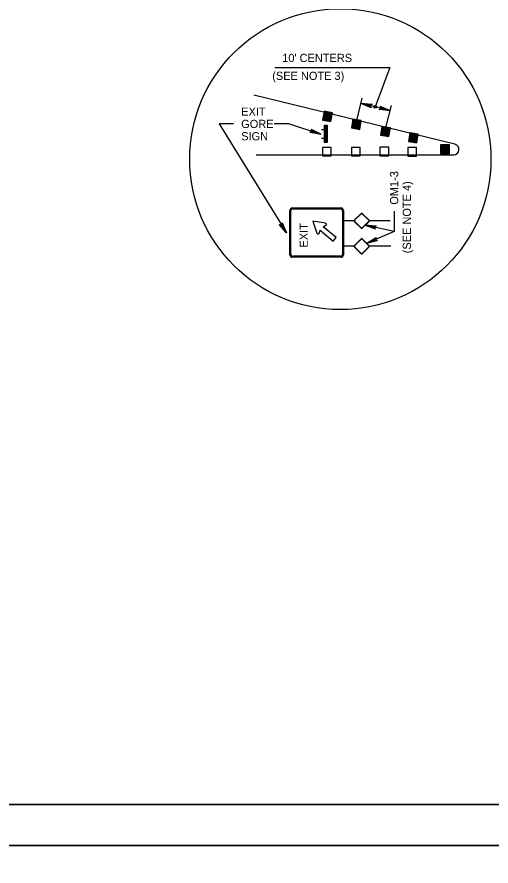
# Model space of a CAD drawing. Extents: x 640253 to 641999, y 298458 to 299646.
# Drawn here: x 641348.1 to 641521.2, y 299044.1 to 299354.5 of the extents above; entities that cross this region are included whole.
import ezdxf

# ---------------------------------------------------------------- set-up
doc = ezdxf.new("R2010")
doc.units = 0
for name, color, linetype in [('1', 7, 'Continuous'), ('2', 7, 'Continuous'), ('PLT-BNDY', 7, 'Continuous')]:
    doc.layers.add(name, color=color, linetype=linetype)

msp = doc.modelspace()

# ---------------------------------------------------------------- linework, layer by layer
at = {"layer": '1'}
for p, q in [((641448.54, 299284.66), (641466.48, 299284.66)), ((641448.77, 299284.33), (641466.25, 299284.33)), ((641447.76, 299267.56), (641447.76, 299283.76)), ((641448.05, 299267.83), (641448.05, 299283.49)), ((641466.97, 299283.49), (641466.97, 299267.83)), ((641467.26, 299283.76), (641467.26, 299267.56)), ((641471.26, 299280.16), (641473.79, 299282.69)), ((641471.39, 299280.15), (641473.81, 299282.56)), ((641474.16, 299282.56), (641476.58, 299280.15)), ((641474.18, 299282.69), (641476.71, 299280.16)), ((641460.69, 299279.14), (641456.07, 299279.87)), ((641456.07, 299279.87), (641457.61, 299275.45)), ((641459.89, 299277.79), (641460.91, 299278.41)), ((641471.18, 299279.96), (641466.97, 299279.96)), ((641473.79, 299277.24), (641471.26, 299279.77)), ((641473.81, 299277.37), (641471.39, 299279.79)), ((641476.58, 299279.79), (641474.16, 299277.37)), ((641476.71, 299279.77), (641474.18, 299277.24)), ((641484.35, 299279.96), (641476.79, 299279.96)), ((641458.38, 299275.37), (641458.79, 299276.49)), ((641458.79, 299276.49), (641463.53, 299272.55)), ((641464.62, 299273.86), (641459.89, 299277.79)), ((641463.53, 299272.55), (641464.62, 299273.86)), ((641471.26, 299270.85), (641473.79, 299273.39)), ((641471.39, 299270.84), (641473.81, 299273.26)), ((641474.16, 299273.26), (641476.58, 299270.84)), ((641474.18, 299273.39), (641476.71, 299270.85)), ((641471.18, 299270.7), (641466.97, 299270.7)), ((641473.79, 299267.93), (641471.26, 299270.47)), ((641473.81, 299268.06), (641471.39, 299270.48)), ((641476.58, 299270.48), (641474.16, 299268.06)), ((641476.71, 299270.47), (641474.18, 299267.93)), ((641484.56, 299270.7), (641476.79, 299270.7)), ((641466.48, 299266.66), (641448.54, 299266.66)), ((641466.25, 299267), (641448.77, 299267)), ((641920.31, 299066.63), (641134.31, 299066.63)), ((641134.31, 299066.63), (641720.31, 299066.63))]:
    msp.add_line(p, q, dxfattribs=at)
for centre, radius, start, end in [((641473.99, 299282.5), 0.275, 45, 135), ((641473.99, 299282.38), 0.252, 45, 135), ((641471.46, 299279.97), 0.275, 135, 225), ((641471.57, 299279.97), 0.252, 135, 225), ((641476.4, 299279.97), 0.252, 315, 45), ((641476.52, 299279.97), 0.275, 315, 45), ((641473.99, 299277.44), 0.275, 225, 315), ((641473.99, 299277.55), 0.252, 225, 315), ((641473.99, 299273.19), 0.275, 45, 135), ((641473.99, 299273.08), 0.252, 45, 135), ((641471.46, 299270.66), 0.275, 135, 225), ((641471.57, 299270.66), 0.252, 135, 225), ((641476.4, 299270.66), 0.252, 315, 45), ((641476.52, 299270.66), 0.275, 315, 45), ((641473.99, 299268.13), 0.275, 225, 315), ((641473.99, 299268.24), 0.252, 225, 315)]:
    msp.add_arc(centre, radius, start, end, dxfattribs=at)
for centre, major_axis, start_param, end_param in [((641448.54, 299283.76), (0, -0.9), 3.141593, 4.712389), ((641448.77, 299283.49), (0, -0.833), 3.141593, 4.712389), ((641466.25, 299283.49), (0, 0.833), 4.712389, 6.283185), ((641466.48, 299283.76), (0, 0.9), 4.712389, 6.283185), ((641460.66, 299278.75), (0.336, -0.279), 6.014589, 8.386103), ((641457.99, 299275.56), (-0.339, 0.282), 1.019875, 3.40872), ((641448.54, 299267.56), (0, -0.9), 4.712389, 6.283185), ((641448.77, 299267.83), (0, -0.833), 4.712389, 6.283185), ((641466.25, 299267.83), (0, 0.833), 3.141593, 4.712389), ((641466.48, 299267.56), (0, 0.9), 3.141593, 4.712389)]:
    msp.add_ellipse(centre, major_axis=major_axis, ratio=0.866667, start_param=start_param, end_param=end_param, dxfattribs=at)
at = {"layer": '2'}
for p, q in [((641508.04, 299307.94), (641434.6, 299325.94)), ((641472.23, 299316.68), (641474.19, 299324.75)), ((641484.34, 299320.29), (641473.74, 299322.88)), ((641482.83, 299314.1), (641484.79, 299322.16)), ((641421.94, 299315.4), (641446.55, 299275.57)), ((641427.15, 299315.4), (641421.94, 299315.4)), ((641460.38, 299313.23), (641459.34, 299313.23)), ((641460.71, 299308.85), (641460.71, 299314.64)), ((641461.05, 299308.77), (641461.05, 299314.73)), ((641460.38, 299310.02), (641459.34, 299310.02)), ((641435.45, 299304.08), (641507.56, 299304.08)), ((641485.84, 299283.45), (641485.84, 299276.05)), ((641485.84, 299276.05), (641475.26, 299278.32)), ((641485.84, 299276.05), (641475.82, 299271.75))]:
    msp.add_line(p, q, dxfattribs=at)
for points in [[(641442.27, 299335.98), (641484.21, 299335.98), (641478.83, 299321.62)], [(641477.3, 299321.52), (641477.23, 299321.82), (641473.74, 299322.88), (641477.3, 299321.52), (641477.45, 299321.32), (641473.74, 299322.88), (641477.32, 299322.19), (641477.51, 299322.43), (641473.74, 299322.88), (641477.75, 299322.55), (641477.51, 299322.43)], [(641480.78, 299321.65), (641480.85, 299321.35), (641484.34, 299320.29), (641480.78, 299321.65), (641480.63, 299321.86), (641484.34, 299320.29), (641480.76, 299320.98), (641480.57, 299320.75), (641484.34, 299320.29), (641480.32, 299320.62), (641480.57, 299320.75)], [(641462.72, 299316.25), (641463.28, 299319.45), (641460.21, 299319.99), (641459.65, 299316.79), (641462.72, 299316.25), (641460.25, 299319.93), (641459.71, 299316.83), (641462.69, 299316.31), (641463.23, 299319.41), (641460.31, 299319.91), (641459.78, 299316.89), (641462.64, 299316.38), (641463.16, 299319.35), (641460.37, 299319.83), (641459.86, 299316.93), (641462.6, 299316.45), (641463.1, 299319.31), (641460.41, 299319.78), (641459.92, 299316.98), (641462.57, 299316.51), (641463.03, 299319.25), (641460.45, 299319.69), (641459.98, 299317.02), (641462.53, 299316.57), (641462.97, 299319.2), (641460.5, 299319.62), (641460.06, 299317.07), (641462.48, 299316.64), (641462.91, 299319.16), (641460.55, 299319.55), (641460.12, 299317.11), (641462.42, 299316.7), (641462.83, 299319.1), (641460.61, 299319.48), (641460.2, 299317.18), (641462.39, 299316.76), (641462.75, 299319.03), (641460.65, 299319.4), (641460.27, 299317.23), (641462.35, 299316.83), (641462.69, 299318.98), (641460.68, 299319.32), (641460.34, 299317.28), (641462.33, 299316.9), (641462.62, 299318.91), (641460.73, 299319.23), (641460.43, 299317.34), (641461.32, 299317.14), (641462.28, 299316.98), (641462.55, 299318.86), (641460.8, 299319.14), (641460.53, 299317.39), (641462.23, 299317.06), (641462.48, 299318.8), (641460.85, 299319.06), (641460.62, 299317.46), (641462.18, 299317.16), (641462.4, 299318.7), (641460.94, 299318.94), (641460.73, 299317.56), (641462.09, 299317.27), (641462.3, 299318.6), (641461, 299318.8), (641460.85, 299317.67), (641462.01, 299317.4), (641462.02, 299317.41), (641462.16, 299318.5), (641461.1, 299318.67), (641460.98, 299317.76), (641461.93, 299317.54), (641462.03, 299318.39), (641461.21, 299318.54), (641461.11, 299317.86), (641461.82, 299317.7), (641461.9, 299318.28), (641461.29, 299318.36), (641461.25, 299317.98), (641461.74, 299317.87), (641461.76, 299318.15), (641461.4, 299318.22), (641461.35, 299318.1), (641461.64, 299318.04)], [(641442.03, 299315.49), (641447.23, 299315.49), (641459.05, 299311.68)], [(641473.25, 299313.37), (641473.81, 299316.57), (641470.73, 299317.11), (641470.18, 299313.91), (641473.25, 299313.37), (641470.78, 299317.05), (641470.24, 299313.96), (641473.22, 299313.44), (641473.76, 299316.53), (641470.84, 299317.04), (641470.31, 299314.01), (641473.17, 299313.51), (641473.69, 299316.47), (641470.9, 299316.95), (641470.39, 299314.05), (641473.13, 299313.57), (641473.63, 299316.43), (641470.94, 299316.9), (641470.45, 299314.1), (641473.09, 299313.64), (641473.56, 299316.37), (641470.98, 299316.82), (641470.51, 299314.15), (641473.06, 299313.69), (641473.5, 299316.33), (641471.03, 299316.74), (641470.58, 299314.19), (641473.01, 299313.76), (641473.43, 299316.28), (641471.08, 299316.68), (641470.65, 299314.24), (641472.95, 299313.82), (641473.36, 299316.22), (641471.14, 299316.61), (641470.73, 299314.3), (641472.92, 299313.88), (641473.28, 299316.15), (641471.17, 299316.52), (641470.8, 299314.35), (641472.88, 299313.95), (641473.22, 299316.1), (641471.21, 299316.45), (641470.87, 299314.4), (641472.86, 299314.03), (641473.15, 299316.03), (641471.26, 299316.36), (641470.96, 299314.47), (641471.85, 299314.27), (641472.81, 299314.1), (641473.08, 299315.98), (641471.33, 299316.26), (641471.05, 299314.51), (641472.76, 299314.18), (641473.01, 299315.92), (641471.38, 299316.18), (641471.15, 299314.59), (641472.71, 299314.28), (641472.93, 299315.83), (641471.47, 299316.06), (641471.26, 299314.68), (641472.62, 299314.4), (641472.82, 299315.72), (641471.53, 299315.93), (641471.38, 299314.79), (641472.54, 299314.53), (641472.54, 299314.53), (641472.69, 299315.62), (641471.63, 299315.8), (641471.51, 299314.88), (641472.46, 299314.66), (641472.56, 299315.51), (641471.74, 299315.66), (641471.64, 299314.98), (641472.35, 299314.82), (641472.43, 299315.4), (641471.82, 299315.48), (641471.77, 299315.1), (641472.27, 299314.99), (641472.29, 299315.28), (641471.93, 299315.34), (641471.88, 299315.23), (641472.17, 299315.16)], [(641455.6, 299313.31), (641455.65, 299313), (641459.05, 299311.68), (641455.6, 299313.31), (641455.47, 299313.52), (641459.05, 299311.68), (641455.53, 299312.64), (641455.32, 299312.42), (641459.05, 299311.68), (641455.07, 299312.31), (641455.32, 299312.42)], [(641483.89, 299310.73), (641484.45, 299313.93), (641481.38, 299314.47), (641480.82, 299311.27), (641483.89, 299310.73), (641481.43, 299314.41), (641480.89, 299311.31), (641483.86, 299310.79), (641484.4, 299313.89), (641481.48, 299314.39), (641480.95, 299311.36), (641483.82, 299310.86), (641484.33, 299313.83), (641481.54, 299314.31), (641481.03, 299311.41), (641483.78, 299310.93), (641484.28, 299313.79), (641481.58, 299314.26), (641481.09, 299311.46), (641483.74, 299310.99), (641484.21, 299313.73), (641481.63, 299314.18), (641481.16, 299311.5), (641483.7, 299311.05), (641484.14, 299313.69), (641481.68, 299314.1), (641481.23, 299311.55), (641483.66, 299311.11), (641484.08, 299313.64), (641481.72, 299314.03), (641481.3, 299311.59), (641483.6, 299311.18), (641484, 299313.58), (641481.79, 299313.97), (641481.37, 299311.66), (641483.57, 299311.24), (641483.93, 299313.51), (641481.82, 299313.88), (641481.44, 299311.71), (641483.52, 299311.31), (641483.87, 299313.45), (641481.86, 299313.8), (641481.52, 299311.76), (641483.5, 299311.38), (641483.8, 299313.39), (641481.91, 299313.71), (641481.6, 299311.82), (641482.5, 299311.63), (641483.46, 299311.45), (641483.72, 299313.34), (641481.97, 299313.62), (641481.7, 299311.87), (641483.41, 299311.54), (641483.65, 299313.28), (641482.02, 299313.54), (641481.8, 299311.94), (641483.35, 299311.64), (641483.58, 299313.18), (641482.11, 299313.42), (641481.9, 299312.04), (641483.26, 299311.75), (641483.47, 299313.08), (641482.18, 299313.29), (641482.03, 299312.15), (641483.19, 299311.88), (641483.19, 299311.89), (641483.34, 299312.98), (641482.28, 299313.15), (641482.15, 299312.24), (641483.1, 299312.02), (641483.2, 299312.87), (641482.39, 299313.02), (641482.28, 299312.34), (641483, 299312.18), (641483.08, 299312.76), (641482.47, 299312.84), (641482.42, 299312.46), (641482.91, 299312.35), (641482.94, 299312.64), (641482.57, 299312.7), (641482.53, 299312.58), (641482.82, 299312.52)], [(641494.09, 299308.44), (641494.65, 299311.64), (641491.58, 299312.18), (641491.02, 299308.98), (641494.09, 299308.44), (641491.62, 299312.11), (641491.08, 299309.02), (641494.06, 299308.5), (641494.6, 299311.6), (641491.68, 299312.11), (641491.15, 299309.07), (641494.01, 299308.58), (641494.53, 299311.54), (641491.74, 299312.02), (641491.23, 299309.12), (641493.98, 299308.64), (641494.48, 299311.49), (641491.78, 299311.97), (641491.29, 299309.17), (641493.94, 299308.7), (641494.41, 299311.44), (641491.82, 299311.88), (641491.36, 299309.21), (641493.9, 299308.76), (641494.34, 299311.39), (641491.87, 299311.81), (641491.43, 299309.26), (641493.85, 299308.83), (641494.28, 299311.35), (641491.92, 299311.74), (641491.49, 299309.3), (641493.8, 299308.89), (641494.2, 299311.29), (641491.98, 299311.67), (641491.57, 299309.36), (641493.77, 299308.95), (641494.12, 299311.22), (641492.02, 299311.59), (641491.64, 299309.42), (641493.72, 299309.02), (641494.06, 299311.16), (641492.06, 299311.52), (641491.71, 299309.47), (641493.7, 299309.09), (641493.99, 299311.1), (641492.11, 299311.42), (641491.8, 299309.53), (641492.69, 299309.33), (641493.66, 299309.16), (641493.92, 299311.05), (641492.17, 299311.33), (641491.9, 299309.58), (641493.61, 299309.25), (641493.85, 299310.99), (641492.22, 299311.25), (641491.99, 299309.65), (641493.55, 299309.35), (641493.78, 299310.89), (641492.31, 299311.13), (641492.1, 299309.75), (641493.46, 299309.46), (641493.67, 299310.79), (641492.38, 299311), (641492.23, 299309.86), (641493.38, 299309.59), (641493.39, 299309.6), (641493.53, 299310.69), (641492.48, 299310.86), (641492.35, 299309.95), (641493.3, 299309.73), (641493.4, 299310.58), (641492.58, 299310.73), (641492.48, 299310.05), (641493.2, 299309.89), (641493.27, 299310.47), (641492.66, 299310.55), (641492.62, 299310.16), (641493.11, 299310.06), (641493.14, 299310.34), (641492.77, 299310.41), (641492.72, 299310.29), (641493.02, 299310.23)], [(641502.75, 299304.61), (641506, 299304.61), (641506, 299307.73), (641502.75, 299307.73), (641502.75, 299304.61), (641505.95, 299307.68), (641502.81, 299307.68), (641502.81, 299304.66), (641505.95, 299304.66), (641505.95, 299307.62), (641502.87, 299307.62), (641502.87, 299304.72), (641505.88, 299304.72), (641505.88, 299307.55), (641502.93, 299307.55), (641502.93, 299304.76), (641505.83, 299304.76), (641505.83, 299307.5), (641502.99, 299307.5), (641502.99, 299304.81), (641505.76, 299304.82), (641505.76, 299307.44), (641503.04, 299307.44), (641503.04, 299304.86), (641505.71, 299304.88), (641505.69, 299307.38), (641503.1, 299307.38), (641503.09, 299304.92), (641505.65, 299304.93), (641505.63, 299307.32), (641503.16, 299307.32), (641503.14, 299304.98), (641505.58, 299305), (641505.58, 299307.25), (641503.23, 299307.26), (641503.2, 299305.02), (641505.49, 299305.06), (641505.5, 299307.2), (641503.3, 299307.2), (641503.26, 299305.08), (641505.43, 299305.11), (641505.43, 299307.15), (641503.36, 299307.14), (641503.33, 299305.11), (641505.36, 299305.17), (641505.35, 299307.09), (641503.43, 299307.06), (641503.39, 299306.14), (641503.39, 299305.17), (641505.29, 299305.23), (641505.27, 299307), (641503.5, 299306.97), (641503.46, 299305.23), (641505.22, 299305.29), (641505.19, 299306.94), (641503.59, 299306.89), (641503.56, 299305.31), (641505.11, 299305.34), (641505.1, 299306.83), (641503.7, 299306.8), (641503.65, 299305.41), (641504.99, 299305.44), (641504.97, 299306.75), (641503.83, 299306.69), (641503.77, 299305.51), (641503.78, 299305.51), (641504.87, 299305.55), (641504.86, 299306.62), (641503.94, 299306.59), (641503.89, 299305.62), (641504.74, 299305.66), (641504.75, 299306.49), (641504.06, 299306.48), (641504.02, 299305.74), (641504.61, 299305.77), (641504.59, 299306.39), (641504.2, 299306.36), (641504.18, 299305.86), (641504.46, 299305.88), (641504.46, 299306.26), (641504.34, 299306.28), (641504.33, 299305.98)], [(641444.9, 299279), (641444.75, 299278.74), (641446.55, 299275.57), (641444.9, 299279), (641444.93, 299279.26), (641446.55, 299275.57), (641444.43, 299278.53), (641444.13, 299278.49), (641446.55, 299275.57), (641443.87, 299278.57), (641444.13, 299278.49)], [(641478.86, 299277.06), (641478.78, 299277.36), (641475.26, 299278.32), (641478.86, 299277.06), (641479.01, 299276.86), (641475.26, 299278.32), (641478.86, 299277.74), (641479.04, 299277.97), (641475.26, 299278.32), (641479.28, 299278.1), (641479.04, 299277.97)], [(641479.49, 299272.79), (641479.25, 299272.99), (641475.82, 299271.75), (641479.49, 299272.79), (641479.73, 299272.72), (641475.82, 299271.75), (641479.1, 299273.34), (641479.11, 299273.64), (641475.82, 299271.75), (641479.23, 299273.89), (641479.11, 299273.64)]]:
    msp.add_lwpolyline(points, dxfattribs=at)
for points in [[(641460.36, 299308.62), (641460.36, 299314.87), (641461.4, 299314.87), (641461.4, 299308.62)], [(641459.61, 299303.68), (641462.86, 299303.68), (641462.86, 299306.8), (641459.61, 299306.8)], [(641470.21, 299303.69), (641473.45, 299303.69), (641473.45, 299306.81), (641470.21, 299306.81)], [(641480.59, 299303.77), (641483.83, 299303.77), (641483.83, 299306.89), (641480.59, 299306.89)], [(641490.76, 299303.58), (641494, 299303.58), (641494, 299306.7), (641490.76, 299306.7)]]:
    msp.add_lwpolyline(points, close=True, dxfattribs=at)
for centre, radius in [((641466.18, 299302.5), 55), ((641478.85, 299321.63), 0.5)]:
    msp.add_circle(centre, radius, dxfattribs=at)
msp.add_arc((641507.56, 299306.04), 1.95, 270, 76.217, dxfattribs=at)
at = {"layer": 'PLT-BNDY'}
for points in [[(641094.31, 299645.63), (641935.31, 299645.63), (641935.31, 299051.63), (641094.31, 299051.63)], [(641094.31, 299051.63), (641935.31, 299051.63), (641935.31, 298457.63), (641094.31, 298457.63)]]:
    msp.add_lwpolyline(points, close=True, dxfattribs=at)

# ---------------------------------------------------------------- texts
at = {"layer": '1'}
msp.add_text('EXIT', height=3, rotation=90, dxfattribs=at).set_placement((641454.29, 299270.2))
at = {"layer": '2'}
for s, p in [("10' CENTERS", (641444.94, 299338)), ('  (SEE NOTE 3)', (641439.07, 299331.46)), ('EXIT', (641429.95, 299318.38)), ('GORE', (641429.95, 299313.88)), ('SIGN', (641429.95, 299309.38))]:
    msp.add_text(s, height=3, dxfattribs=at).set_placement(p)
for s, p in [('OM1-3', (641487.32, 299285.85)), ('(SEE NOTE 4)', (641491.95, 299268.1))]:
    msp.add_text(s, height=3, rotation=90, dxfattribs=at).set_placement(p)

doc.saveas('drawing.dxf')
